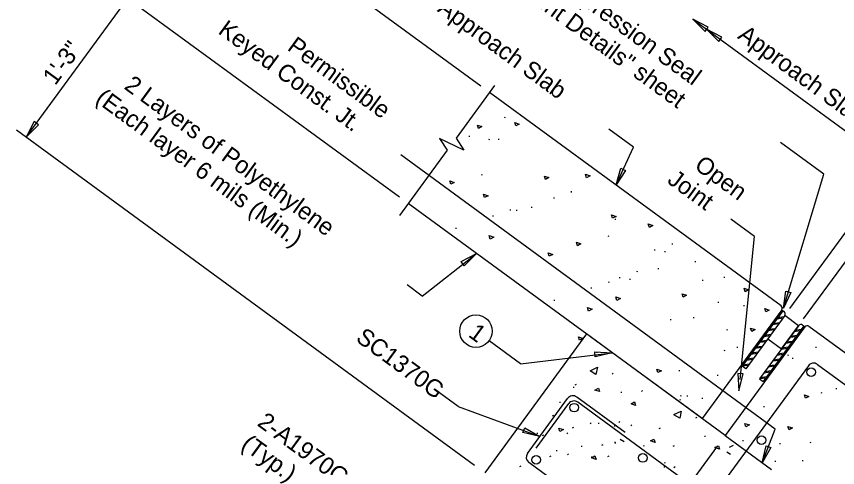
# Model space of a CAD drawing. Extents: x 1970654 to 1970899, y 796145 to 796378.
# Drawn here: x 1970800.62 to 1970824.47, y 796236.18 to 796249.28 of the extents above; entities that cross this region are included whole.
import ezdxf

# ---------------------------------------------------------------- set-up
doc = ezdxf.new("R2010")
doc.units = 0
for name, color, linetype in [('BR_AUTO DIMENSION', 7, 'Continuous'), ('BR_CONCRETE', 7, 'Continuous'), ('BR_DETAILS', 7, 'Continuous'), ('BR_REBAR', 7, 'Continuous'), ('BR_STRUCTURAL STEEL', 7, 'Continuous'), ('BR_TABLE LINES', 7, 'Continuous'), ('BR_TEXT', 7, 'Continuous')]:
    doc.layers.add(name, color=color, linetype=linetype)

msp = doc.modelspace()

# ---------------------------------------------------------------- linework, layer by layer
at = {"layer": 'BR_AUTO DIMENSION'}
for p, q in [((1970805.933, 796253.248), (1970814.104, 796247.265)), ((1970800.901, 796245.778), (1970806.217, 796253.04)), ((1970803.57, 796250.02), (1970811.741, 796244.038)), ((1970820.265, 796249.202), (1970826.108, 796244.924)), ((1970823.084, 796240.794), (1970827.126, 796246.315)), ((1970800.616, 796245.986), (1970813.923, 796236.244)), ((1970818.542, 796245.483), (1970817.831, 796246.004)), ((1970823.487, 796240.499), (1970827.529, 796246.02)), ((1970824.069, 796244.7), (1970822.811, 796245.621)), ((1970822.663, 796237.297), (1970811.783, 796245.263)), ((1970818.037, 796244.386), (1970818.542, 796245.483)), ((1970822.901, 796240.803), (1970824.069, 796244.7)), ((1970822.062, 796242.887), (1970821.374, 796243.39)), ((1970821.638, 796238.74), (1970822.062, 796242.887)), ((1970812.407, 796241.156), (1970813.98, 796242.399)), ((1970812.407, 796241.156), (1970811.964, 796241.481)), ((1970815.265, 796239.189), (1970814.346, 796239.861)), ((1970815.265, 796239.189), (1970817.922, 796239.513)), ((1970813.449, 796237.947), (1970812.841, 796238.392)), ((1970813.449, 796237.947), (1970815.821, 796237.081)), ((1970822.286, 796236.317), (1970822.663, 796237.297)), ((1970816.823, 796231.114), (1970820.99, 796236.805))]:
    msp.add_line(p, q, dxfattribs=at)
for points in [[(1970820.713, 796248.967), (1970820.265, 796249.202), (1970820.624, 796248.846)], [(1970821.111, 796248.676), (1970820.663, 796248.911), (1970821.022, 796248.555)], [(1970801.136, 796246.226), (1970800.901, 796245.778), (1970801.257, 796246.137)], [(1970818.314, 796244.809), (1970818.037, 796244.386), (1970818.178, 796244.872)], [(1970813.534, 796242.16), (1970813.98, 796242.399), (1970813.624, 796242.04)], [(1970823.116, 796241.261), (1970822.901, 796240.803), (1970822.973, 796241.304)], [(1970817.417, 796239.541), (1970817.922, 796239.513), (1970817.431, 796239.391)], [(1970821.579, 796238.913), (1970821.607, 796238.408), (1970821.728, 796238.899)], [(1970815.384, 796237.335), (1970815.821, 796237.081), (1970815.328, 796237.196)], [(1970822.536, 796236.757), (1970822.286, 796236.317), (1970822.396, 796236.811)]]:
    msp.add_lwpolyline(points, close=True, dxfattribs=at)
msp.add_circle((1970813.966, 796240.14), 0.472, dxfattribs=at)
at = {"layer": 'BR_CONCRETE'}
for p, q in [((1970822.833, 796240.875), (1970814.362, 796247.076)), ((1970820.537, 796237.598), (1970812, 796243.849)), ((1970822.851, 796240.758), (1970820.537, 796237.598)), ((1970823.523, 796240.266), (1970821.21, 796237.106)), ((1970823.64, 796240.284), (1970827.153, 796237.712)), ((1970817.175, 796240.06), (1970814.222, 796236.025)), ((1970821.21, 796237.106), (1970817.175, 796240.06)), ((1970821.21, 796237.106), (1970822.554, 796236.121))]:
    msp.add_line(p, q, dxfattribs=at)
for centre, start, end in [((1970822.784, 796240.808), 323.7906, 53.8011), ((1970823.591, 796240.217), 53.7906, 143.7906)]:
    msp.add_arc(centre, 0.0833, start, end, dxfattribs=at)
at = {"layer": 'BR_DETAILS'}
for p, q in [((1970814.51, 796247.278), (1970813.387, 796245.744)), ((1970814.81, 796246.34), (1970814.811, 796246.37)), ((1970813.777, 796245.786), (1970813.778, 796245.816)), ((1970814.355, 796245.698), (1970814.356, 796245.728)), ((1970814.633, 796245.695), (1970814.634, 796245.725)), ((1970813.131, 796245.394), (1970811.741, 796243.496)), ((1970814.141, 796244.67), (1970814.143, 796244.7)), ((1970816.743, 796244.172), (1970816.744, 796244.202)), ((1970816.236, 796243.992), (1970816.238, 796244.022)), ((1970814.973, 796243.646), (1970814.975, 796243.676)), ((1970815.157, 796243.635), (1970815.158, 796243.665)), ((1970815.587, 796243.724), (1970815.588, 796243.754)), ((1970814.467, 796243.467), (1970814.468, 796243.497)), ((1970818.018, 796243.375), (1970818.02, 796243.405)), ((1970813.387, 796243.109), (1970813.388, 796243.139)), ((1970817.822, 796242.886), (1970817.823, 796242.916)), ((1970819.673, 796242.66), (1970819.674, 796242.69)), ((1970819.166, 796242.481), (1970819.167, 796242.511)), ((1970819.464, 796242.43), (1970819.465, 796242.46)), ((1970820.345, 796242.145), (1970820.346, 796242.175)), ((1970819.267, 796241.94), (1970819.268, 796241.97)), ((1970818.147, 796241.683), (1970818.148, 796241.713)), ((1970818.653, 796241.862), (1970818.655, 796241.892)), ((1970821.188, 796241.691), (1970821.189, 796241.721)), ((1970817.831, 796241.554), (1970817.832, 796241.584)), ((1970818.444, 796241.632), (1970818.446, 796241.662)), ((1970820.557, 796241.599), (1970820.558, 796241.629)), ((1970817.324, 796241.375), (1970817.325, 796241.405)), ((1970816.245, 796241.017), (1970816.246, 796241.047)), ((1970821.01, 796240.962), (1970821.012, 796240.992)), ((1970821.756, 796240.862), (1970821.757, 796240.892)), ((1970819.628, 796240.46), (1970819.629, 796240.49)), ((1970820.299, 796240.516), (1970820.3, 796240.546)), ((1970821.269, 796240.165), (1970821.27, 796240.195)), ((1970817.479, 796239.54), (1970817.477, 796239.51)), ((1970821.192, 796239.571), (1970821.194, 796239.601)), ((1970821.566, 796239.659), (1970821.567, 796239.689)), ((1970823.848, 796239.654), (1970823.849, 796239.684)), ((1970817.459, 796239.427), (1970817.458, 796239.397)), ((1970823.041, 796239.431), (1970823.043, 796239.461)), ((1970823.176, 796239.333), (1970823.177, 796239.363)), ((1970817.921, 796238.897), (1970817.956, 796238.917)), ((1970819.878, 796238.978), (1970819.88, 796239.008)), ((1970820.993, 796238.844), (1970820.994, 796238.874)), ((1970816.853, 796238.58), (1970816.888, 796238.6)), ((1970816.8, 796238.526), (1970816.798, 796238.496)), ((1970818.183, 796238.375), (1970818.182, 796238.345)), ((1970818.773, 796238.391), (1970818.809, 796238.412)), ((1970824.01, 796238.339), (1970824.011, 796238.369)), ((1970824.444, 796238.454), (1970824.445, 796238.484)), ((1970819.895, 796238.155), (1970819.894, 796238.125)), ((1970819.914, 796238.268), (1970819.913, 796238.238)), ((1970820.11, 796238.237), (1970820.112, 796238.267)), ((1970820.549, 796238.172), (1970820.551, 796238.202)), ((1970816.404, 796238.087), (1970816.403, 796238.057)), ((1970822.337, 796237.931), (1970822.339, 796237.961)), ((1970816.193, 796237.679), (1970816.229, 796237.699)), ((1970820.356, 796237.625), (1970820.392, 796237.646)), ((1970817.283, 796237.455), (1970817.318, 796237.476)), ((1970817.523, 796237.474), (1970817.522, 796237.444)), ((1970817.999, 796237.4), (1970817.98, 796237.367)), ((1970818.114, 796237.49), (1970818.149, 796237.511)), ((1970818.462, 796237.402), (1970818.497, 796237.422)), ((1970815.744, 796237.186), (1970815.743, 796237.156)), ((1970816.603, 796237.167), (1970816.638, 796237.188)), ((1970816.772, 796237.328), (1970816.808, 796237.349)), ((1970819.289, 796237.308), (1970819.324, 796237.329)), ((1970815.904, 796237.112), (1970815.939, 796237.132)), ((1970818.005, 796236.926), (1970818.004, 796236.896)), ((1970818.013, 796236.909), (1970818.012, 796236.879)), ((1970818.271, 796236.923), (1970818.157, 796236.992)), ((1970820.619, 796237.103), (1970820.618, 796237.073)), ((1970821.209, 796237.12), (1970821.245, 796237.14)), ((1970821.733, 796236.946), (1970821.734, 796236.976)), ((1970823.69, 796236.894), (1970823.691, 796236.924)), ((1970816.314, 796236.656), (1970816.315, 796236.686)), ((1970817.034, 796236.806), (1970817.033, 796236.776)), ((1970817.625, 796236.823), (1970817.66, 796236.843)), ((1970818.84, 796236.815), (1970818.838, 796236.785)), ((1970819.698, 796236.797), (1970819.734, 796236.817)), ((1970821.33, 796236.773), (1970821.45, 796236.831)), ((1970822.805, 796236.856), (1970822.806, 796236.886)), ((1970816.114, 796236.5), (1970816.149, 796236.52)), ((1970816.623, 796236.554), (1970816.659, 796236.575)), ((1970817.34, 796236.498), (1970817.321, 796236.466)), ((1970817.802, 796236.501), (1970817.838, 796236.521)), ((1970821.366, 796236.552), (1970821.252, 796236.621)), ((1970815.244, 796236.211), (1970815.28, 796236.231)), ((1970819.431, 796236.208), (1970819.43, 796236.178)), ((1970819.451, 796236.321), (1970819.449, 796236.291)), ((1970819.719, 796236.183), (1970819.754, 796236.204)), ((1970822.666, 796236.346), (1970822.667, 796236.376)), ((1970823.464, 796236.365), (1970823.465, 796236.395))]:
    msp.add_line(p, q, dxfattribs=at)
for points in [[(1970814.14, 796246.081), (1970814.039, 796246.026), (1970814.008, 796246.126), (1970814.14, 796246.081)], [(1970815.225, 796246.158), (1970815.123, 796246.103), (1970815.092, 796246.203), (1970815.225, 796246.158)], [(1970813.387, 796245.744), (1970813.613, 796245.399), (1970812.905, 796245.738), (1970813.131, 796245.394)], [(1970816.087, 796244.602), (1970815.985, 796244.547), (1970815.955, 796244.647), (1970816.087, 796244.602)], [(1970817.282, 796244.654), (1970817.18, 796244.599), (1970817.15, 796244.699), (1970817.282, 796244.654)], [(1970813.338, 796244.461), (1970813.236, 796244.407), (1970813.206, 796244.506), (1970813.338, 796244.461)], [(1970814.317, 796244.076), (1970814.216, 796244.022), (1970814.185, 796244.121), (1970814.317, 796244.076)], [(1970818.038, 796243.475), (1970817.936, 796243.42), (1970817.906, 796243.52), (1970818.038, 796243.475)], [(1970819.106, 796243.211), (1970819.004, 796243.156), (1970818.973, 796243.256), (1970819.106, 796243.211)], [(1970814.484, 796242.872), (1970814.382, 796242.817), (1970814.352, 796242.917), (1970814.484, 796242.872)], [(1970817.018, 796242.677), (1970816.917, 796242.623), (1970816.886, 796242.722), (1970817.018, 796242.677)], [(1970816.196, 796242.369), (1970816.094, 796242.315), (1970816.064, 796242.414), (1970816.196, 796242.369)], [(1970820.087, 796241.182), (1970819.985, 796241.128), (1970819.955, 796241.227), (1970820.087, 796241.182)], [(1970821.887, 796241.339), (1970821.785, 796241.285), (1970821.755, 796241.384), (1970821.887, 796241.339)], [(1970818.164, 796241.088), (1970818.063, 796241.033), (1970818.032, 796241.133), (1970818.164, 796241.088)], [(1970817.342, 796240.78), (1970817.24, 796240.725), (1970817.21, 796240.825), (1970817.342, 796240.78)], [(1970822.488, 796240.752), (1970822.386, 796240.697), (1970822.356, 796240.797), (1970822.488, 796240.752)], [(1970822.079, 796240.185), (1970821.977, 796240.13), (1970821.947, 796240.23), (1970822.079, 796240.185)], [(1970817.077, 796239.931), (1970816.975, 796239.877), (1970816.945, 796239.976), (1970817.077, 796239.931)], [(1970817.28, 796238.986), (1970817.496, 796239.091), (1970817.451, 796238.882), (1970817.283, 796238.984)], [(1970819.356, 796238.989), (1970819.255, 796238.934), (1970819.224, 796239.034), (1970819.356, 796238.989)], [(1970817.423, 796238.428), (1970817.525, 796238.482), (1970817.556, 796238.383), (1970817.423, 796238.428)], [(1970823.641, 796238.246), (1970823.539, 796238.191), (1970823.509, 796238.291), (1970823.641, 796238.246)], [(1970818.472, 796238.029), (1970818.574, 796238.084), (1970818.604, 796237.984), (1970818.472, 796238.029)], [(1970819.716, 796237.714), (1970819.932, 796237.819), (1970819.887, 796237.61), (1970819.719, 796237.712)], [(1970821.909, 796237.414), (1970821.807, 796237.359), (1970821.777, 796237.459), (1970821.909, 796237.414)], [(1970816.508, 796237.281), (1970816.406, 796237.226), (1970816.376, 796237.326), (1970816.508, 796237.281)], [(1970823.165, 796237.327), (1970823.063, 796237.273), (1970823.032, 796237.372), (1970823.165, 796237.327)], [(1970819.037, 796236.951), (1970819.139, 796237.005), (1970819.169, 796236.905), (1970819.037, 796236.951)], [(1970820.908, 796236.757), (1970821.009, 796236.812), (1970821.04, 796236.712), (1970820.908, 796236.757)], [(1970817.323, 796236.46), (1970817.425, 796236.515), (1970817.455, 796236.415), (1970817.323, 796236.46)]]:
    msp.add_lwpolyline(points, dxfattribs=at)
at = {"layer": 'BR_REBAR'}
for p, q in [((1970823.624, 796239.134), (1970819.441, 796233.421)), ((1970823.886, 796239.174), (1970826.407, 796237.328)), ((1970815.461, 796236.589), (1970816.631, 796238.186)), ((1970818.301, 796237.195), (1970816.893, 796238.227)), ((1970816.007, 796237.141), (1970816.661, 796238.035)), ((1970827.556, 796230.291), (1970816.923, 796238.075)), ((1970815.712, 796236.737), (1970816.007, 796237.141)), ((1970826.226, 796228.475), (1970815.502, 796236.327))]:
    msp.add_line(p, q, dxfattribs=at)
for centre in [(1970823.707, 796238.945), (1970816.821, 796237.918), (1970822.261, 796236.97), (1970815.713, 796236.405), (1970818.817, 796236.456)]:
    msp.add_circle(centre, 0.125, dxfattribs=at)
for centre, radius, start, end in [((1970823.775, 796239.023), 0.188, 53.7906, 143.7906), ((1970816.782, 796238.075), 0.188, 53.7906, 143.7906), ((1970816.813, 796237.924), 0.188, 53.7906, 143.7906), ((1970815.613, 796236.478), 0.187, 143.7906, 233.7906)]:
    msp.add_arc(centre, radius, start, end, dxfattribs=at)
at = {"layer": 'BR_STRUCTURAL STEEL'}
for p, q in [((1970822.882, 796240.519), (1970822.708, 796240.492)), ((1970822.908, 796240.555), (1970822.734, 796240.528)), ((1970822.757, 796240.348), (1970822.582, 796240.321)), ((1970822.783, 796240.383), (1970822.608, 796240.356)), ((1970822.506, 796240.005), (1970822.331, 796239.978)), ((1970822.532, 796240.04), (1970822.357, 796240.013)), ((1970822.631, 796240.176), (1970822.457, 796240.149)), ((1970822.657, 796240.212), (1970822.483, 796240.185)), ((1970823.287, 796240.014), (1970823.112, 796239.987)), ((1970823.387, 796240.15), (1970823.212, 796240.123)), ((1970823.413, 796240.186), (1970823.238, 796240.159)), ((1970822.38, 796239.833), (1970822.205, 796239.806)), ((1970822.406, 796239.869), (1970822.231, 796239.842)), ((1970823.136, 796239.807), (1970822.961, 796239.78)), ((1970823.162, 796239.843), (1970822.987, 796239.816)), ((1970823.261, 796239.978), (1970823.086, 796239.951)), ((1970822.255, 796239.662), (1970822.08, 796239.635)), ((1970822.281, 796239.697), (1970822.106, 796239.67)), ((1970823.01, 796239.635), (1970822.835, 796239.608)), ((1970823.036, 796239.671), (1970822.861, 796239.644)), ((1970822.003, 796239.319), (1970821.829, 796239.291)), ((1970822.029, 796239.354), (1970821.855, 796239.327)), ((1970822.129, 796239.49), (1970821.954, 796239.463)), ((1970822.155, 796239.526), (1970821.98, 796239.499)), ((1970822.759, 796239.292), (1970822.584, 796239.265)), ((1970822.785, 796239.328), (1970822.61, 796239.301)), ((1970822.884, 796239.464), (1970822.71, 796239.437)), ((1970822.91, 796239.5), (1970822.736, 796239.472)), ((1970821.878, 796239.147), (1970821.703, 796239.12)), ((1970821.904, 796239.183), (1970821.729, 796239.156)), ((1970822.633, 796239.121), (1970822.459, 796239.094)), ((1970822.659, 796239.156), (1970822.485, 796239.129)), ((1970822.408, 796238.813), (1970822.233, 796238.786)), ((1970822.508, 796238.949), (1970822.333, 796238.922)), ((1970822.534, 796238.985), (1970822.359, 796238.958)), ((1970822.382, 796238.778), (1970822.207, 796238.751))]:
    msp.add_line(p, q, dxfattribs=at)
for points in [[(1970822.918, 796240.709), (1970822.885, 796240.734), (1970821.703, 796239.12)], [(1970822.936, 796240.593), (1970821.804, 796239.046), (1970821.703, 796239.12)], [(1970823.34, 796240.297), (1970822.207, 796238.751), (1970822.308, 796238.677)], [(1970823.456, 796240.315), (1970823.49, 796240.291), (1970822.308, 796238.677)]]:
    msp.add_lwpolyline(points, dxfattribs=at)
for centre, start, end in [((1970822.869, 796240.642), 323.7906, 53.7906), ((1970823.407, 796240.248), 53.7906, 143.7906)]:
    msp.add_arc(centre, 0.0833, start, end, dxfattribs=at)
at = {"layer": 'BR_TABLE LINES'}
msp.add_lwpolyline([(1970823.34, 796240.297), (1970822.936, 796240.593), (1970822.444, 796239.92), (1970822.847, 796239.625)], close=True, dxfattribs=at)

# ---------------------------------------------------------------- texts
at = {"layer": 'BR_AUTO DIMENSION'}
msp.add_text('1\'-3"', height=0.5, rotation=53.7906, dxfattribs=at).set_placement((1970801.744, 796247.256))
at = {"layer": 'BR_TEXT'}
for s, height, p in [('For Details, see "Compression Seal ', 0.49995, (1970811.749, 796253.498)), ('Expansion Joint Details" sheet', 0.49995, (1970812.557, 796251.915)), ('Top of Approach Slab', 0.49995, (1970811.142, 796250.675)), ('Keyed Const. Jt.', 0.49995, (1970806.447, 796248.808)), ('Approach Slab', 0.49995, (1970821.542, 796248.665)), ('Permissible', 0.49995, (1970808.457, 796248.328)), ('2 Layers of Polyethylene', 0.49995, (1970803.718, 796247.2)), ('(Each layer 6 mils (Min.)', 0.49995, (1970802.882, 796246.821)), ('Open', 0.4999, (1970820.282, 796244.88)), ('Joint', 0.4999, (1970819.495, 796244.465)), ('1', 0.5, (1970813.718, 796240.001)), ('SC1370G', 0.4999, (1970810.446, 796239.873)), ('2-A1970G', 0.4999, (1970807.586, 796237.416)), ('(Typ.)', 0.4999, (1970807.113, 796236.769))]:
    msp.add_text(s, height=height, rotation=323.7906, dxfattribs=at).set_placement(p)

doc.saveas('drawing.dxf')
